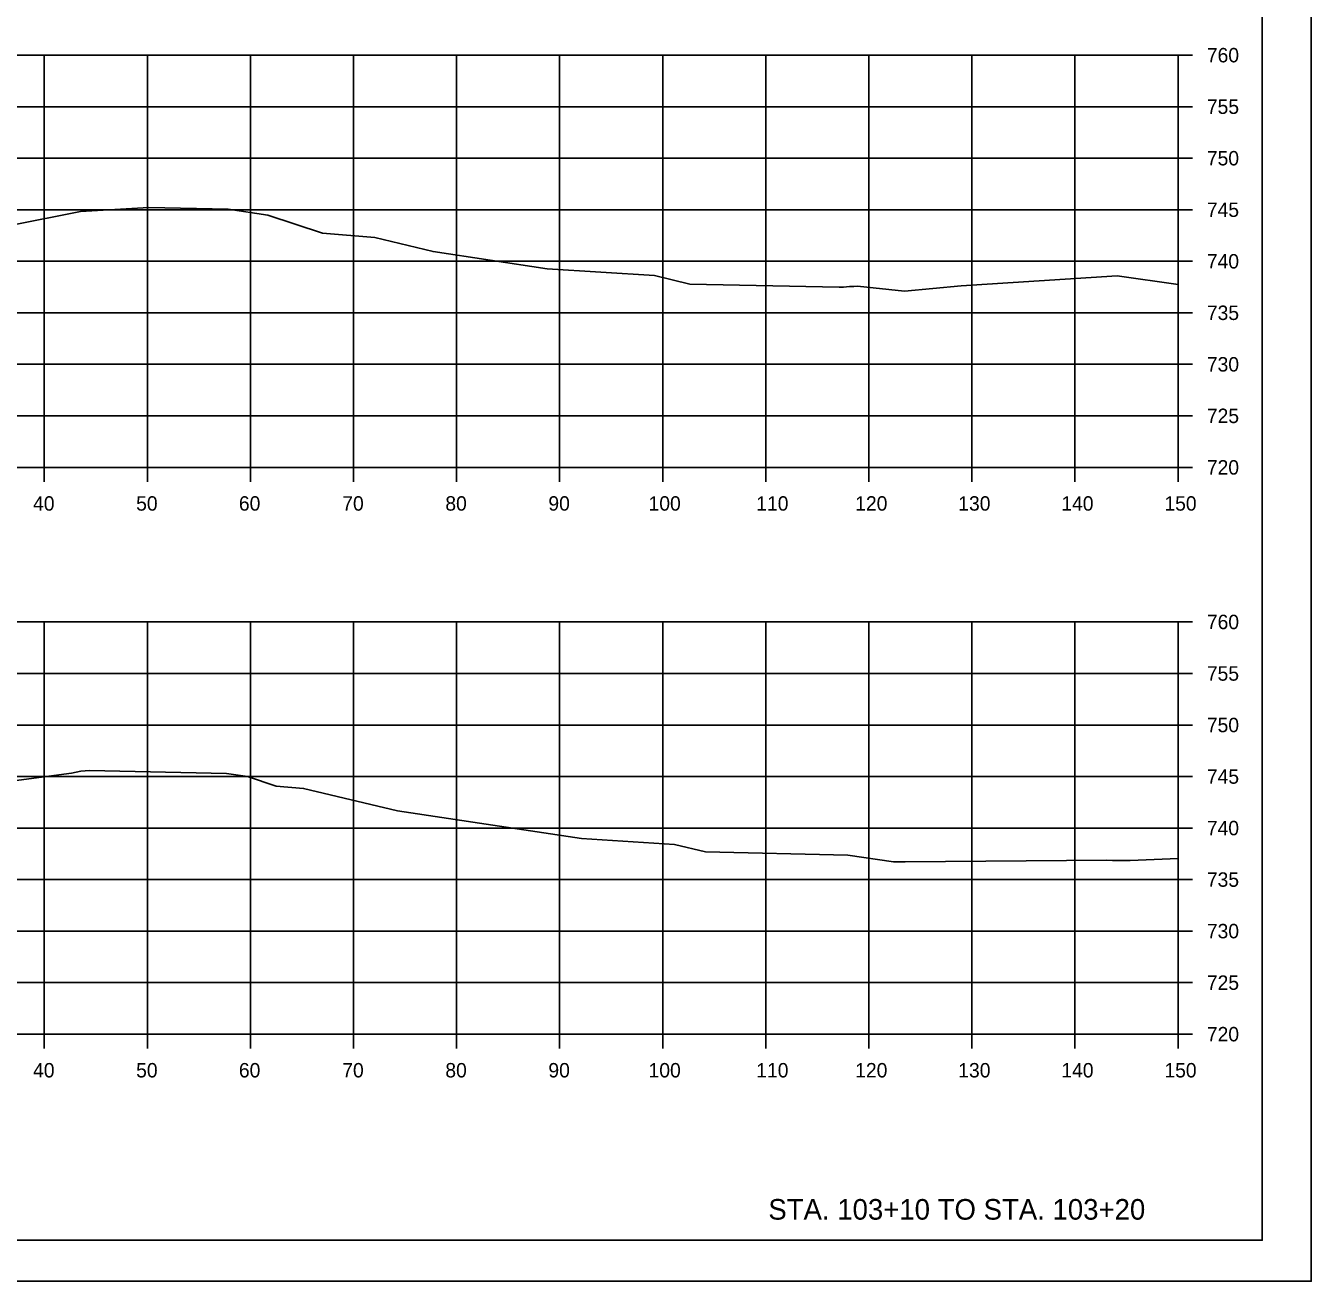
# Model space of a CAD drawing. Extents: x 1202951 to 1376887, y 378065 to 728038.
# Drawn here: x 1374323.2 to 1374447.9, y 378759.9 to 378881.8 of the extents above; entities that cross this region are included whole.
import ezdxf

# ---------------------------------------------------------------- set-up
doc = ezdxf.new("R2010")
doc.units = 0
for name, color, linetype in [('R_Axis', 7, 'Continuous'), ('R_Axis Annot', 7, 'Continuous'), ('R_Draft', 7, 'Continuous'), ('R_Exist Surface', 7, 'Continuous'), ('R_Grid', 7, 'Continuous'), ('R_No Plot', 7, 'Continuous')]:
    doc.layers.add(name, color=color, linetype=linetype)

msp = doc.modelspace()

# ---------------------------------------------------------------- linework, layer by layer
at = {"layer": 'R_Axis'}
for p, q in [((1374434.98, 378838.92), (1374434.98, 378878.92)), ((1374436.38, 378878.92), (1374434.98, 378878.92)), ((1374436.38, 378873.92), (1374434.98, 378873.92)), ((1374436.38, 378868.92), (1374434.98, 378868.92)), ((1374436.38, 378863.92), (1374434.98, 378863.92)), ((1374436.38, 378858.92), (1374434.98, 378858.92)), ((1374436.38, 378853.92), (1374434.98, 378853.92)), ((1374436.38, 378848.92), (1374434.98, 378848.92)), ((1374436.38, 378843.92), (1374434.98, 378843.92)), ((1374134.98, 378838.92), (1374434.98, 378838.92)), ((1374324.98, 378837.52), (1374324.98, 378838.92)), ((1374334.98, 378837.52), (1374334.98, 378838.92)), ((1374344.98, 378837.52), (1374344.98, 378838.92)), ((1374354.98, 378837.52), (1374354.98, 378838.92)), ((1374364.98, 378837.52), (1374364.98, 378838.92)), ((1374374.98, 378837.52), (1374374.98, 378838.92)), ((1374384.98, 378837.52), (1374384.98, 378838.92)), ((1374394.98, 378837.52), (1374394.98, 378838.92)), ((1374404.98, 378837.52), (1374404.98, 378838.92)), ((1374414.98, 378837.52), (1374414.98, 378838.92)), ((1374424.98, 378837.52), (1374424.98, 378838.92)), ((1374434.98, 378837.52), (1374434.98, 378838.92)), ((1374436.38, 378838.92), (1374434.98, 378838.92)), ((1374434.98, 378783.92), (1374434.98, 378823.92)), ((1374436.38, 378823.92), (1374434.98, 378823.92)), ((1374436.38, 378818.92), (1374434.98, 378818.92)), ((1374436.38, 378813.92), (1374434.98, 378813.92)), ((1374436.38, 378808.92), (1374434.98, 378808.92)), ((1374436.38, 378803.92), (1374434.98, 378803.92)), ((1374436.38, 378798.92), (1374434.98, 378798.92)), ((1374436.38, 378793.92), (1374434.98, 378793.92)), ((1374436.38, 378788.92), (1374434.98, 378788.92)), ((1374134.98, 378783.92), (1374434.98, 378783.92)), ((1374324.98, 378782.52), (1374324.98, 378783.92)), ((1374334.98, 378782.52), (1374334.98, 378783.92)), ((1374344.98, 378782.52), (1374344.98, 378783.92)), ((1374354.98, 378782.52), (1374354.98, 378783.92)), ((1374364.98, 378782.52), (1374364.98, 378783.92)), ((1374374.98, 378782.52), (1374374.98, 378783.92)), ((1374384.98, 378782.52), (1374384.98, 378783.92)), ((1374394.98, 378782.52), (1374394.98, 378783.92)), ((1374404.98, 378782.52), (1374404.98, 378783.92)), ((1374414.98, 378782.52), (1374414.98, 378783.92)), ((1374424.98, 378782.52), (1374424.98, 378783.92)), ((1374434.98, 378782.52), (1374434.98, 378783.92)), ((1374436.38, 378783.92), (1374434.98, 378783.92))]:
    msp.add_line(p, q, dxfattribs=at)
at = {"layer": 'R_Exist Surface'}
for points in [[(1374321.66, 378862.39), (1374328.5, 378863.74), (1374335.13, 378864.15), (1374342.81, 378863.99), (1374346.68, 378863.39), (1374351.98, 378861.64), (1374357.05, 378861.22), (1374362.7, 378859.86), (1374373.77, 378858.2), (1374384.17, 378857.54), (1374387.63, 378856.71), (1374402.09, 378856.4), (1374402.54, 378856.42), (1374403.11, 378856.46), (1374403.53, 378856.47), (1374403.87, 378856.51), (1374408.43, 378856.02), (1374413.95, 378856.53), (1374429.09, 378857.51), (1374434.98, 378856.68)], [(1374316.65, 378807.8), (1374327.62, 378809.26), (1374328.52, 378809.44), (1374329.38, 378809.49), (1374342.66, 378809.22), (1374344.69, 378808.91), (1374347.47, 378807.99), (1374350.14, 378807.77), (1374359.25, 378805.58), (1374377.09, 378802.9), (1374386.13, 378802.32), (1374389.14, 378801.6), (1374402.96, 378801.3), (1374407.37, 378800.64), (1374408.5, 378800.64), (1374428.07, 378800.79), (1374428.64, 378800.78), (1374430.35, 378800.76), (1374434.98, 378800.96)]]:
    msp.add_lwpolyline(points, dxfattribs=at)
at = {"layer": 'R_Grid'}
for p, q in [((1374134.98, 378878.92), (1374434.98, 378878.92)), ((1374324.98, 378838.92), (1374324.98, 378878.92)), ((1374334.98, 378838.92), (1374334.98, 378878.92)), ((1374344.98, 378838.92), (1374344.98, 378878.92)), ((1374354.98, 378838.92), (1374354.98, 378878.92)), ((1374364.98, 378838.92), (1374364.98, 378878.92)), ((1374374.98, 378838.92), (1374374.98, 378878.92)), ((1374384.98, 378838.92), (1374384.98, 378878.92)), ((1374394.98, 378838.92), (1374394.98, 378878.92)), ((1374404.98, 378838.92), (1374404.98, 378878.92)), ((1374414.98, 378838.92), (1374414.98, 378878.92)), ((1374424.98, 378838.92), (1374424.98, 378878.92)), ((1374434.98, 378838.92), (1374434.98, 378878.92)), ((1374134.98, 378873.92), (1374434.98, 378873.92)), ((1374134.98, 378868.92), (1374434.98, 378868.92)), ((1374134.98, 378863.92), (1374434.98, 378863.92)), ((1374134.98, 378858.92), (1374434.98, 378858.92)), ((1374134.98, 378853.92), (1374434.98, 378853.92)), ((1374134.98, 378848.92), (1374434.98, 378848.92)), ((1374134.98, 378843.92), (1374434.98, 378843.92)), ((1374134.98, 378838.92), (1374434.98, 378838.92)), ((1374134.98, 378823.92), (1374434.98, 378823.92)), ((1374324.98, 378783.92), (1374324.98, 378823.92)), ((1374334.98, 378783.92), (1374334.98, 378823.92)), ((1374344.98, 378783.92), (1374344.98, 378823.92)), ((1374354.98, 378783.92), (1374354.98, 378823.92)), ((1374364.98, 378783.92), (1374364.98, 378823.92)), ((1374374.98, 378783.92), (1374374.98, 378823.92)), ((1374384.98, 378783.92), (1374384.98, 378823.92)), ((1374394.98, 378783.92), (1374394.98, 378823.92)), ((1374404.98, 378783.92), (1374404.98, 378823.92)), ((1374414.98, 378783.92), (1374414.98, 378823.92)), ((1374424.98, 378783.92), (1374424.98, 378823.92)), ((1374434.98, 378783.92), (1374434.98, 378823.92)), ((1374134.98, 378818.92), (1374434.98, 378818.92)), ((1374134.98, 378813.92), (1374434.98, 378813.92)), ((1374134.98, 378808.92), (1374434.98, 378808.92)), ((1374134.98, 378803.92), (1374434.98, 378803.92)), ((1374134.98, 378798.92), (1374434.98, 378798.92)), ((1374134.98, 378793.92), (1374434.98, 378793.92)), ((1374134.98, 378788.92), (1374434.98, 378788.92)), ((1374134.98, 378783.92), (1374434.98, 378783.92))]:
    msp.add_line(p, q, dxfattribs=at)
at = {"layer": 'R_No Plot'}
for p, q in [((1374443.16, 378763.92), (1374443.16, 378969.38)), ((1374443.16, 378763.92), (1374126.98, 378763.92)), ((1374114.58, 378759.94), (1374447.91, 378759.94))]:
    msp.add_line(p, q, dxfattribs=at)
for points in [[(1374114.57, 378973.28), (1374447.91, 378973.28), (1374447.91, 378759.94), (1374114.57, 378759.94)], [(1374360.9, 378969.38), (1374380.52, 378969.38), (1374380.52, 378959.5), (1374396.63, 378959.5), (1374419.83, 378959.5), (1374419.83, 378935.17), (1374443.16, 378935.17), (1374443.16, 378763.92), (1374126.98, 378763.92), (1374126.98, 378969.38)]]:
    msp.add_lwpolyline(points, close=True, dxfattribs=at)

# ---------------------------------------------------------------- texts
at = {"layer": 'R_Axis Annot'}
for s, p in [('760', (1374437.78, 378878.22)), ('755', (1374437.78, 378873.22)), ('750', (1374437.78, 378868.22)), ('745', (1374437.78, 378863.22)), ('740', (1374437.78, 378858.22)), ('735', (1374437.78, 378853.22)), ('730', (1374437.78, 378848.22)), ('725', (1374437.78, 378843.22)), ('720', (1374437.78, 378838.22)), ('40', (1374323.89, 378834.72)), ('50', (1374333.89, 378834.72)), ('60', (1374343.86, 378834.72)), ('70', (1374353.89, 378834.72)), ('80', (1374363.89, 378834.72)), ('90', (1374373.89, 378834.72)), ('100', (1374383.61, 378834.72)), ('110', (1374394.06, 378834.72)), ('120', (1374403.66, 378834.72)), ('130', (1374413.66, 378834.72)), ('140', (1374423.66, 378834.72)), ('150', (1374433.66, 378834.72)), ('760', (1374437.78, 378823.22)), ('755', (1374437.78, 378818.22)), ('750', (1374437.78, 378813.22)), ('745', (1374437.78, 378808.22)), ('740', (1374437.78, 378803.22)), ('735', (1374437.78, 378798.22)), ('730', (1374437.78, 378793.22)), ('725', (1374437.78, 378788.22)), ('720', (1374437.78, 378783.22)), ('40', (1374323.89, 378779.72)), ('50', (1374333.89, 378779.72)), ('60', (1374343.86, 378779.72)), ('70', (1374353.89, 378779.72)), ('80', (1374363.89, 378779.72)), ('90', (1374373.89, 378779.72)), ('100', (1374383.61, 378779.72)), ('110', (1374394.06, 378779.72)), ('120', (1374403.66, 378779.72)), ('130', (1374413.66, 378779.72)), ('140', (1374423.66, 378779.72)), ('150', (1374433.66, 378779.72))]:
    msp.add_text(s, height=1.4, dxfattribs=at).set_placement(p)
at = {"layer": 'R_Draft'}
msp.add_text('STA. 103+10 TO STA. 103+20', height=2, dxfattribs=at).set_placement((1374395.23, 378765.92))

doc.saveas('drawing.dxf')
